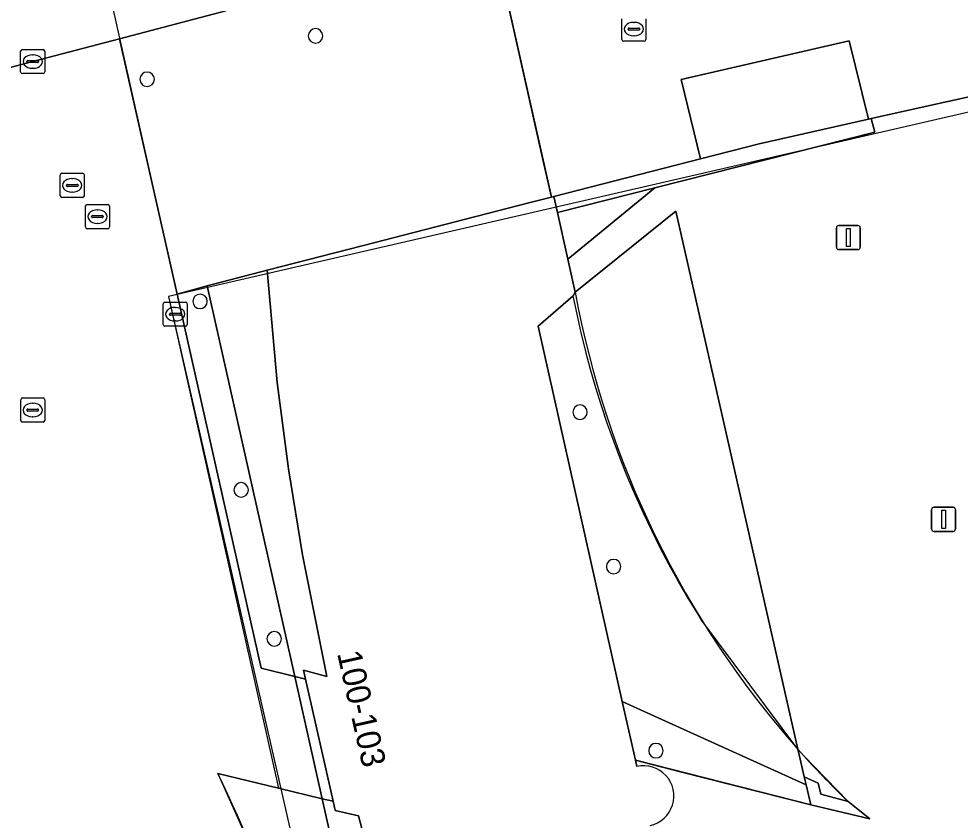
# Model space of a CAD drawing. Extents: x 160806 to 161707, y 383696 to 384148.
# Drawn here: x 161397.72 to 161436.72, y 383897.18 to 383930.37 of the extents above; entities that cross this region are included whole.
import ezdxf

# ---------------------------------------------------------------- set-up
doc = ezdxf.new("R2010")
doc.units = 0
for name, color, linetype in [('IMGEO_Hek', 7, 'Continuous'), ('IMGEO_Kolk', 7, 'Continuous'), ('IMGEO_Lichtmast', 7, 'Continuous'), ('IMGEO_Lijnafwatering', 7, 'Continuous'), ('IMGEO_Muur', 7, 'Continuous'), ('IMGEO_OVBaan_gesloten', 7, 'Continuous'), ('IMGEO_Pand', 7, 'Continuous'), ('IMGEO_Pand_nummerreeks', 7, 'Continuous'), ('IMGEO_Pand_overbouw', 7, 'Continuous'), ('IMGEO_Rijbaan_lokaal_open', 7, 'Continuous'), ('IMGEO_Rioolput', 7, 'Continuous'), ('IMGEO_Voetgangersgebied_open', 7, 'Continuous'), ('IMGEO_Voetpad_open', 7, 'Continuous')]:
    doc.layers.add(name, color=color, linetype=linetype)

msp = doc.modelspace()

# ---------------------------------------------------------------- linework, layer by layer
at = {"layer": 'IMGEO_Hek'}
for points in [[(161405.527, 383919.308), (161408.013, 383919.96)], [(161409.16, 383903.134), (161405.527, 383919.308)], [(161410.296, 383898.071), (161409.16, 383903.134)], [(161418.7, 383860.601), (161410.296, 383898.071)]]:
    msp.add_lwpolyline(points, dxfattribs=at)
at = {"layer": 'IMGEO_Kolk'}
for p, q in [((161397.8, 383928.172), (161397.8, 383929.024)), ((161397.875, 383929.098), (161398.727, 383929.098)), ((161398.288, 383928.878), (161398.313, 383928.878)), ((161398.801, 383929.024), (161398.801, 383928.172)), ((161398.059, 383928.592), (161398.059, 383928.604)), ((161398.497, 383928.555), (161398.099, 383928.555)), ((161398.102, 383928.641), (161398.5, 383928.641)), ((161398.543, 383928.604), (161398.543, 383928.592)), ((161398.727, 383928.098), (161397.875, 383928.098)), ((161398.311, 383928.318), (161398.286, 383928.318)), ((161403.703, 383917.71), (161403.703, 383918.562)), ((161403.778, 383918.636), (161404.63, 383918.636)), ((161404.191, 383918.416), (161404.216, 383918.416)), ((161404.704, 383918.562), (161404.704, 383917.71)), ((161403.962, 383918.13), (161403.962, 383918.142)), ((161404.4, 383918.093), (161404.002, 383918.093)), ((161404.005, 383918.179), (161404.403, 383918.179)), ((161404.446, 383918.142), (161404.446, 383918.13)), ((161404.63, 383917.636), (161403.778, 383917.636)), ((161404.214, 383917.856), (161404.189, 383917.856))]:
    msp.add_line(p, q, dxfattribs=at)
for points in [[(161397.8, 383928.172), (161397.8, 383929.024)], [(161397.875, 383929.098), (161398.727, 383929.098)], [(161398.801, 383929.024), (161398.801, 383928.172)], [(161398.727, 383928.098), (161397.875, 383928.098)], [(161403.703, 383917.71), (161403.703, 383918.562)], [(161403.778, 383918.636), (161404.63, 383918.636)], [(161404.704, 383918.562), (161404.704, 383917.71)], [(161404.63, 383917.636), (161403.778, 383917.636)]]:
    msp.add_lwpolyline(points, dxfattribs=at)
for centre, radius, start, end in [((161397.877, 383929.022), 0.0765, 91.552, 178.448), ((161397.877, 383929.022), 0.0765, 91.552, 178.448), ((161398.725, 383929.022), 0.0765, 1.552, 88.448), ((161398.725, 383929.022), 0.0765, 1.552, 88.448), ((161398.099, 383928.601), 0.0403, 85.8775, 175.7526), ((161398.096, 383928.591), 0.0366, 178.938, 274.7102), ((161398.5, 383928.598), 0.043, 264.8664, 352.4533), ((161398.504, 383928.603), 0.0386, 1.7309, 96.639), ((161397.877, 383928.174), 0.0765, 181.552, 268.448), ((161397.877, 383928.174), 0.0765, 181.552, 268.448), ((161398.725, 383928.174), 0.0765, 271.552, 358.448), ((161398.725, 383928.174), 0.0765, 271.552, 358.448), ((161403.78, 383918.56), 0.0765, 91.552, 178.448), ((161403.78, 383918.56), 0.0765, 91.552, 178.448), ((161404.628, 383918.56), 0.0765, 1.552, 88.448), ((161404.628, 383918.56), 0.0765, 1.552, 88.448), ((161404.002, 383918.139), 0.0403, 85.8775, 175.7526), ((161403.999, 383918.129), 0.0366, 178.938, 274.7102), ((161404.403, 383918.136), 0.043, 264.8664, 352.4533), ((161404.407, 383918.141), 0.0386, 1.7309, 96.639), ((161403.78, 383917.712), 0.0765, 181.552, 268.448), ((161403.78, 383917.712), 0.0765, 181.552, 268.448), ((161404.628, 383917.712), 0.0765, 271.552, 358.448), ((161404.628, 383917.712), 0.0765, 271.552, 358.448)]:
    msp.add_arc(centre, radius, start, end, dxfattribs=at)
for centre, major_axis, ratio, start_param, end_param in [((161398.287, 383928.598), (-0.387, 0.002), 0.722429, 4.712389, 7.853982), ((161398.312, 383928.598), (-0.39, 0.002), 0.717154, 1.570796, 4.712389), ((161404.19, 383918.136), (-0.387, 0.002), 0.722429, 4.712389, 7.853982), ((161404.215, 383918.136), (-0.39, 0.002), 0.717154, 1.570796, 4.712389)]:
    msp.add_ellipse(centre, major_axis=major_axis, ratio=ratio, start_param=start_param, end_param=end_param, dxfattribs=at)
at = {"layer": 'IMGEO_Lichtmast'}
for p, q in [((161431.693, 383921.809), (161432.483, 383921.809)), ((161432.483, 383921.809), (161431.693, 383921.809)), ((161431.593, 383920.909), (161431.593, 383921.709)), ((161431.593, 383921.709), (161431.593, 383920.909)), ((161432.583, 383921.709), (161432.583, 383920.909)), ((161432.583, 383920.909), (161432.583, 383921.709)), ((161432.483, 383920.809), (161431.693, 383920.809)), ((161431.693, 383920.809), (161432.483, 383920.809)), ((161435.637, 383910.143), (161436.427, 383910.143)), ((161436.427, 383910.143), (161435.637, 383910.143)), ((161435.537, 383909.243), (161435.537, 383910.043)), ((161435.537, 383910.043), (161435.537, 383909.243)), ((161436.527, 383910.043), (161436.527, 383909.243)), ((161436.527, 383909.243), (161436.527, 383910.043)), ((161436.427, 383909.143), (161435.637, 383909.143)), ((161435.637, 383909.143), (161436.427, 383909.143))]:
    msp.add_line(p, q, dxfattribs=at)
for points in [[(161432.013, 383921.684), (161432.163, 383921.684), (161432.163, 383920.934), (161432.013, 383920.934), (161432.013, 383921.684)], [(161435.957, 383910.018), (161436.107, 383910.018), (161436.107, 383909.268), (161435.957, 383909.268), (161435.957, 383910.018)]]:
    msp.add_lwpolyline(points, dxfattribs=at)
for centre, start, end in [((161431.693, 383921.709), 90, 180), ((161431.693, 383921.709), 90, 180), ((161432.483, 383921.709), 0, 90), ((161432.483, 383921.709), 360, 90), ((161431.693, 383920.909), 180, 270), ((161431.693, 383920.909), 180, 270), ((161432.483, 383920.909), 270, 0), ((161432.483, 383920.909), 270, 0), ((161435.637, 383910.043), 90, 180), ((161435.637, 383910.043), 90, 180), ((161436.427, 383910.043), 0, 90), ((161436.427, 383910.043), 360, 90), ((161435.637, 383909.243), 180, 270), ((161435.637, 383909.243), 180, 270), ((161436.427, 383909.243), 270, 0), ((161436.427, 383909.243), 270, 0)]:
    msp.add_arc(centre, 0.1, start, end, dxfattribs=at)
at = {"layer": 'IMGEO_Lijnafwatering'}
msp.add_lwpolyline([(161403.923, 383918.874), (161408.481, 383898.51)], dxfattribs=at)
at = {"layer": 'IMGEO_Muur'}
msp.add_lwpolyline([(161433.038, 383926.234), (161439.383, 383927.651)], dxfattribs=at)
msp.add_lwpolyline([(161433.18, 383925.675), (161433.038, 383926.234), (161432.923, 383926.208), (161428.39, 383925.195), (161425.968, 383924.573), (161419.888, 383923.011), (161420.037, 383922.345), (161424.076, 383923.368)], close=True, dxfattribs=at)
at = {"layer": 'IMGEO_OVBaan_gesloten'}
msp.add_lwpolyline([(161389.01, 383930.33), (161396.1, 383928.014), (161398.301, 383928.598), (161401.899, 383929.545), (161406.303, 383930.704), (161406.292, 383930.768), (161411.273, 383932.069), (161417.389, 383933.655), (161422.223, 383934.908), (161436.084, 383938.543)], dxfattribs=at)
at = {"layer": 'IMGEO_Pand'}
msp.add_lwpolyline([(161423.327, 383899.403), (161423.268, 383899.662), (161422.721, 383902.1), (161419.234, 383917.635), (161420.694, 383918.894), (161420.775, 383919.046), (161420.469, 383920.416), (161420.037, 383922.345), (161419.888, 383923.011), (161419.786, 383922.985), (161418.849, 383922.744), (161411.952, 383920.972), (161408.013, 383919.96), (161408.426, 383915.311), (161408.889, 383911.729), (161409.47, 383908.166), (161410.484, 383903.138), (161409.523, 383903.401), (161409.607, 383903.025), (161410.742, 383897.964), (161410.827, 383897.586), (161411.798, 383897.366), (161413.557, 383890.652)], dxfattribs=at)
for centre, radius, start, end in [((161410.016, 383929.66), 0.3, 90, 270), ((161410.016, 383929.66), 0.3, 270, 90), ((161403.04, 383927.864), 0.3, 90, 270), ((161403.04, 383927.864), 0.3, 270, 90), ((161405.23, 383918.667), 0.3, 90, 270), ((161405.23, 383918.667), 0.3, 270, 90), ((161420.973, 383914.079), 0.3, 90, 270), ((161420.973, 383914.079), 0.3, 270, 90), ((161406.935, 383910.86), 0.3, 90, 270), ((161406.935, 383910.86), 0.3, 270, 90), ((161422.364, 383907.682), 0.3, 90, 270), ((161422.364, 383907.682), 0.3, 270, 90), ((161408.305, 383904.694), 0.3, 90, 270), ((161408.305, 383904.694), 0.3, 270, 90), ((161424.117, 383900.061), 0.3, 90, 270), ((161424.117, 383900.061), 0.3, 270, 90), ((161423.607, 383898.183), 1.252, 282.3385, 102.9475)]:
    msp.add_arc(centre, radius, start, end, dxfattribs=at)
at = {"layer": 'IMGEO_Pand_overbouw'}
for points in [[(161576.544, 383863.524), (161556.299, 383953.974), (161403.923, 383918.874), (161417.58, 383859.039), (161456.542, 383836.683)], [(161410.484, 383903.138), (161409.47, 383908.166), (161408.889, 383911.729), (161408.426, 383915.311), (161408.026, 383919.819), (161408.013, 383919.96), (161411.952, 383920.972), (161418.849, 383922.744), (161419.786, 383922.985), (161419.437, 383924.536), (161417.522, 383933.062), (161417.086, 383935.004), (161401.461, 383931.49), (161401.894, 383929.568), (161407.767, 383903.471), (161409.16, 383903.134), (161409.607, 383903.025), (161409.523, 383903.401)], [(161432.972, 383897.242), (161432.074, 383897.956), (161430.247, 383899.844), (161429.992, 383900.129), (161426.025, 383905.451), (161425.874, 383905.688), (161425.459, 383906.371), (161425.058, 383907.061), (161424.671, 383907.76), (161424.299, 383908.467), (161423.941, 383909.18), (161423.598, 383909.9), (161423.271, 383910.627), (161422.958, 383911.359), (161422.661, 383912.097), (161422.38, 383912.839), (161422.114, 383913.586), (161421.863, 383914.337), (161421.629, 383915.091), (161421.41, 383915.848), (161421.215, 383916.58), (161421.208, 383916.607), (161421.021, 383917.368), (161420.849, 383918.131), (161420.694, 383918.894), (161419.234, 383917.635), (161422.721, 383902.1), (161423.268, 383899.662), (161425.13, 383899.181), (161430.54, 383897.812)], [(161405.973, 383899.115), (161408.052, 383894.445), (161409.909, 383889.683), (161411.541, 383884.838), (161412.522, 383881.497), (161413.685, 383876.957), (161417.567, 383859.679), (161418.7, 383860.601), (161424.012, 383864.925), (161421.322, 383870.26), (161418.342, 383876.968), (161415.742, 383883.762), (161414.609, 383887.201), (161413.557, 383890.652), (161411.798, 383897.366), (161410.827, 383897.586), (161410.742, 383897.964), (161410.296, 383898.071), (161408.481, 383898.51)]]:
    msp.add_lwpolyline(points, close=True, dxfattribs=at)
at = {"layer": 'IMGEO_Rijbaan_lokaal_open'}
for points in [[(161425.161, 383927.855), (161432.12, 383929.454), (161432.923, 383926.208), (161433.038, 383926.234), (161439.383, 383927.651), (161437.201, 383937.461), (161436.914, 383938.751), (161436.084, 383938.543), (161422.223, 383934.908), (161417.389, 383933.655), (161417.522, 383933.062), (161419.786, 383922.985), (161419.888, 383923.011), (161425.968, 383924.573)], [(161417.522, 383933.062), (161417.389, 383933.655), (161411.273, 383932.069), (161406.292, 383930.768), (161406.303, 383930.704), (161401.899, 383929.545), (161404.279, 383918.971), (161405.527, 383919.308), (161408.013, 383919.96), (161411.952, 383920.972), (161418.849, 383922.744), (161419.786, 383922.985)], [(161425.968, 383924.573), (161428.39, 383925.195), (161432.923, 383926.208), (161432.12, 383929.454), (161425.161, 383927.855)]]:
    msp.add_lwpolyline(points, close=True, dxfattribs=at)
msp.add_lwpolyline([(161405.973, 383899.115), (161408.481, 383898.51), (161410.296, 383898.071), (161409.16, 383903.134), (161407.767, 383903.471), (161404.279, 383918.971), (161401.899, 383929.545), (161398.301, 383928.598), (161396.1, 383928.014)], dxfattribs=at)
for centre, radius, start, end in [((161410.016, 383929.66), 0.3, 90, 270), ((161410.016, 383929.66), 0.3, 270, 90), ((161403.04, 383927.864), 0.3, 90, 270), ((161403.04, 383927.864), 0.3, 270, 90), ((161307.805, 383852.606), 108.628, 17.2609, 25.35045)]:
    msp.add_arc(centre, radius, start, end, dxfattribs=at)
at = {"layer": 'IMGEO_Rioolput'}
for p, q in [((161422.704, 383929.515), (161422.704, 383930.367)), ((161423.705, 383930.367), (161423.705, 383929.515)), ((161423.006, 383929.984), (161423.404, 383929.984)), ((161423.192, 383930.221), (161423.217, 383930.221)), ((161422.963, 383929.935), (161422.963, 383929.947)), ((161423.401, 383929.898), (161423.003, 383929.898)), ((161423.215, 383929.661), (161423.19, 383929.661)), ((161423.447, 383929.947), (161423.447, 383929.935)), ((161423.631, 383929.441), (161422.779, 383929.441)), ((161399.437, 383923.044), (161399.437, 383923.896)), ((161399.512, 383923.97), (161400.364, 383923.97)), ((161399.925, 383923.75), (161399.95, 383923.75)), ((161400.438, 383923.896), (161400.438, 383923.044)), ((161399.696, 383923.464), (161399.696, 383923.476)), ((161400.134, 383923.427), (161399.736, 383923.427)), ((161399.739, 383923.513), (161400.137, 383923.513)), ((161400.18, 383923.476), (161400.18, 383923.464)), ((161400.364, 383922.97), (161399.512, 383922.97)), ((161399.948, 383923.19), (161399.923, 383923.19)), ((161400.482, 383921.751), (161400.482, 383922.603)), ((161400.557, 383922.677), (161401.409, 383922.677)), ((161401.483, 383922.603), (161401.483, 383921.751)), ((161400.741, 383922.171), (161400.741, 383922.183)), ((161400.784, 383922.22), (161401.182, 383922.22)), ((161400.97, 383922.457), (161400.995, 383922.457)), ((161401.225, 383922.183), (161401.225, 383922.171)), ((161401.179, 383922.134), (161400.781, 383922.134)), ((161400.993, 383921.897), (161400.968, 383921.897)), ((161401.409, 383921.677), (161400.557, 383921.677)), ((161397.801, 383913.74), (161397.801, 383914.592)), ((161397.876, 383914.666), (161398.728, 383914.666)), ((161398.289, 383914.446), (161398.314, 383914.446)), ((161398.802, 383914.592), (161398.802, 383913.74)), ((161398.06, 383914.16), (161398.06, 383914.172)), ((161398.498, 383914.123), (161398.1, 383914.123)), ((161398.103, 383914.209), (161398.501, 383914.209)), ((161398.544, 383914.172), (161398.544, 383914.16)), ((161398.728, 383913.666), (161397.876, 383913.666)), ((161398.312, 383913.886), (161398.287, 383913.886))]:
    msp.add_line(p, q, dxfattribs=at)
for points in [[(161422.704, 383929.515), (161422.704, 383930.367)], [(161423.705, 383930.367), (161423.705, 383929.515)], [(161423.631, 383929.441), (161422.779, 383929.441)], [(161399.437, 383923.044), (161399.437, 383923.896)], [(161399.512, 383923.97), (161400.364, 383923.97)], [(161400.438, 383923.896), (161400.438, 383923.044)], [(161400.364, 383922.97), (161399.512, 383922.97)], [(161400.482, 383921.751), (161400.482, 383922.603)], [(161400.557, 383922.677), (161401.409, 383922.677)], [(161401.483, 383922.603), (161401.483, 383921.751)], [(161401.409, 383921.677), (161400.557, 383921.677)], [(161397.801, 383913.74), (161397.801, 383914.592)], [(161397.876, 383914.666), (161398.728, 383914.666)], [(161398.802, 383914.592), (161398.802, 383913.74)], [(161398.728, 383913.666), (161397.876, 383913.666)]]:
    msp.add_lwpolyline(points, dxfattribs=at)
for centre, radius, start, end in [((161423.003, 383929.944), 0.0403, 85.8775, 175.7526), ((161423.408, 383929.946), 0.0386, 1.7309, 96.639), ((161423, 383929.934), 0.0366, 178.938, 274.7102), ((161423.404, 383929.941), 0.043, 264.8664, 352.4533), ((161422.781, 383929.517), 0.0765, 181.552, 268.448), ((161422.781, 383929.517), 0.0765, 181.552, 268.448), ((161423.629, 383929.517), 0.0765, 271.552, 358.448), ((161423.629, 383929.517), 0.0765, 271.552, 358.448), ((161399.514, 383923.894), 0.0765, 91.552, 178.448), ((161399.514, 383923.894), 0.0765, 91.552, 178.448), ((161400.362, 383923.894), 0.0765, 1.552, 88.448), ((161400.362, 383923.894), 0.0765, 1.552, 88.448), ((161399.736, 383923.473), 0.0403, 85.8775, 175.7526), ((161399.733, 383923.463), 0.0366, 178.938, 274.7102), ((161400.137, 383923.47), 0.043, 264.8664, 352.4533), ((161400.141, 383923.475), 0.0386, 1.7309, 96.639), ((161399.514, 383923.046), 0.0765, 181.552, 268.448), ((161399.514, 383923.046), 0.0765, 181.552, 268.448), ((161400.362, 383923.046), 0.0765, 271.552, 358.448), ((161400.362, 383923.046), 0.0765, 271.552, 358.448), ((161400.559, 383922.601), 0.0765, 91.552, 178.448), ((161400.559, 383922.601), 0.0765, 91.552, 178.448), ((161401.407, 383922.601), 0.0765, 1.552, 88.448), ((161401.407, 383922.601), 0.0765, 1.552, 88.448), ((161400.781, 383922.18), 0.0403, 85.8775, 175.7526), ((161400.778, 383922.17), 0.0366, 178.938, 274.7102), ((161401.182, 383922.177), 0.043, 264.8664, 352.4533), ((161401.186, 383922.182), 0.0386, 1.7309, 96.639), ((161400.559, 383921.753), 0.0765, 181.552, 268.448), ((161400.559, 383921.753), 0.0765, 181.552, 268.448), ((161401.407, 383921.753), 0.0765, 271.552, 358.448), ((161401.407, 383921.753), 0.0765, 271.552, 358.448), ((161397.878, 383914.59), 0.0765, 91.552, 178.448), ((161397.878, 383914.59), 0.0765, 91.552, 178.448), ((161398.726, 383914.59), 0.0765, 1.552, 88.448), ((161398.726, 383914.59), 0.0765, 1.552, 88.448), ((161398.1, 383914.169), 0.0403, 85.8775, 175.7526), ((161398.097, 383914.159), 0.0366, 178.938, 274.7102), ((161398.501, 383914.166), 0.043, 264.8664, 352.4533), ((161398.505, 383914.171), 0.0386, 1.7309, 96.639), ((161397.878, 383913.742), 0.0765, 181.552, 268.448), ((161397.878, 383913.742), 0.0765, 181.552, 268.448), ((161398.726, 383913.742), 0.0765, 271.552, 358.448), ((161398.726, 383913.742), 0.0765, 271.552, 358.448)]:
    msp.add_arc(centre, radius, start, end, dxfattribs=at)
for centre, major_axis, ratio, start_param, end_param in [((161423.191, 383929.941), (-0.387, 0.002), 0.722429, 4.712389, 7.853982), ((161423.216, 383929.941), (-0.39, 0.002), 0.717154, 1.570796, 4.712389), ((161399.924, 383923.47), (-0.387, 0.002), 0.722429, 4.712389, 7.853982), ((161399.949, 383923.47), (-0.39, 0.002), 0.717154, 1.570796, 4.712389), ((161400.969, 383922.177), (-0.387, 0.002), 0.722429, 4.712389, 7.853982), ((161400.994, 383922.177), (-0.39, 0.002), 0.717154, 1.570796, 4.712389), ((161398.288, 383914.166), (-0.387, 0.002), 0.722429, 4.712389, 7.853982), ((161398.313, 383914.166), (-0.39, 0.002), 0.717154, 1.570796, 4.712389)]:
    msp.add_ellipse(centre, major_axis=major_axis, ratio=ratio, start_param=start_param, end_param=end_param, dxfattribs=at)
at = {"layer": 'IMGEO_Voetgangersgebied_open'}
for points in [[(161502.28, 383941.387), (161484.102, 383937.319), (161484.378, 383936.019), (161477.167, 383934.318), (161476.856, 383935.709), (161454.819, 383930.799), (161459.978, 383907.51), (161460.12, 383906.88), (161462.516, 383896.238), (161457.261, 383891.97), (161448.9, 383885.137), (161443.236, 383910.469), (161439.383, 383927.651), (161433.038, 383926.234), (161433.18, 383925.675), (161424.076, 383923.368), (161420.469, 383920.416), (161420.775, 383919.046), (161424.946, 383922.401), (161429.992, 383900.129), (161430.119, 383899.986), (161430.247, 383899.844)], [(161432.074, 383897.956), (161432.972, 383897.242), (161430.54, 383897.812), (161423.268, 383899.662), (161423.327, 383899.403)]]:
    msp.add_lwpolyline(points, dxfattribs=at)
for centre, radius, start, end in [((161459.898, 383926.709), 40.012, 222.1779, 225.9407), ((161423.607, 383898.183), 1.252, 282.3385, 102.9475)]:
    msp.add_arc(centre, radius, start, end, dxfattribs=at)
at = {"layer": 'IMGEO_Voetpad_open'}
for points in [[(161420.037, 383922.345), (161420.469, 383920.416), (161424.076, 383923.368)], [(161405.527, 383919.308), (161409.16, 383903.134), (161409.607, 383903.025), (161409.523, 383903.401), (161410.484, 383903.138), (161409.47, 383908.166), (161408.889, 383911.729), (161408.426, 383915.311), (161408.013, 383919.96)], [(161409.16, 383903.134), (161405.527, 383919.308), (161404.279, 383918.971), (161407.767, 383903.471)], [(161410.296, 383898.071), (161410.742, 383897.964), (161409.607, 383903.025), (161409.16, 383903.134)], [(161430.334, 383898.65), (161424.672, 383901.216), (161422.721, 383902.1), (161423.268, 383899.662), (161430.54, 383897.812)], [(161432.074, 383897.956), (161430.947, 383898.256), (161430.836, 383898.71), (161430.253, 383898.977), (161430.334, 383898.65), (161430.54, 383897.812), (161432.972, 383897.242)], [(161415.742, 383883.762), (161414.609, 383887.201), (161413.557, 383890.652), (161411.798, 383897.366), (161410.827, 383897.586), (161410.742, 383897.964), (161410.296, 383898.071), (161418.7, 383860.601), (161423.289, 383864.336), (161424.012, 383864.925), (161421.322, 383870.26), (161418.342, 383876.968)]]:
    msp.add_lwpolyline(points, close=True, dxfattribs=at)
for points in [[(161429.992, 383900.129), (161424.946, 383922.401), (161420.775, 383919.046)], [(161420.775, 383919.046), (161420.694, 383918.894), (161419.234, 383917.635), (161422.721, 383902.1), (161424.672, 383901.216), (161430.334, 383898.65), (161430.253, 383898.977), (161430.087, 383899.713), (161429.992, 383900.129)], [(161430.247, 383899.844), (161430.119, 383899.986), (161429.992, 383900.129), (161430.087, 383899.713), (161430.253, 383898.977), (161430.836, 383898.71), (161430.947, 383898.256), (161432.074, 383897.956)], [(161411.541, 383884.838), (161412.522, 383881.497), (161413.685, 383876.957), (161417.567, 383859.679), (161418.7, 383860.601), (161410.296, 383898.071), (161408.481, 383898.51), (161405.973, 383899.115)]]:
    msp.add_lwpolyline(points, dxfattribs=at)
for centre, radius, start, end in [((161405.23, 383918.667), 0.3, 90, 270), ((161405.23, 383918.667), 0.3, 270, 90), ((161459.294, 383926.11), 39.161, 190.3917, 221.5621), ((161459.294, 383926.11), 39.161, 190.3917, 221.5621), ((161420.973, 383914.079), 0.3, 90, 270), ((161420.973, 383914.079), 0.3, 270, 90), ((161406.935, 383910.86), 0.3, 90, 270), ((161406.935, 383910.86), 0.3, 270, 90), ((161422.364, 383907.682), 0.3, 90, 270), ((161422.364, 383907.682), 0.3, 270, 90), ((161408.305, 383904.694), 0.3, 90, 270), ((161408.305, 383904.694), 0.3, 270, 90), ((161424.117, 383900.061), 0.3, 90, 270), ((161424.117, 383900.061), 0.3, 270, 90), ((161459.898, 383926.709), 40.012, 222.1779, 225.9407), ((161307.805, 383852.606), 108.628, 17.2609, 25.35045)]:
    msp.add_arc(centre, radius, start, end, dxfattribs=at)

# ---------------------------------------------------------------- texts
at = {"layer": 'IMGEO_Pand_nummerreeks'}
msp.add_text('100-103', height=1, rotation=282.6392, dxfattribs=at).set_placement((161410.905, 383904.094))

doc.saveas('drawing.dxf')
